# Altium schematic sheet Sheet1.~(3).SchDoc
size A4
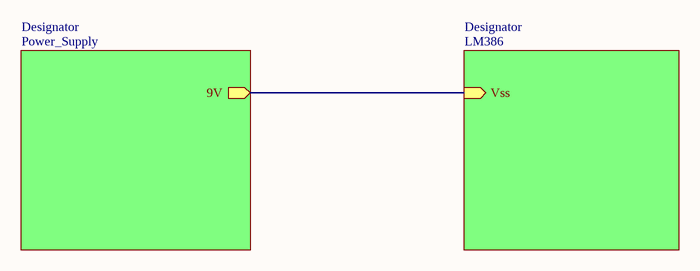
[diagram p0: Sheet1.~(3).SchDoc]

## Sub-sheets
Designator = Power_Supply: 9V (out)
Designator = LM386: Vss (in)

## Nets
(unnamed): sheet Designator/9V, sheet Designator/Vss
